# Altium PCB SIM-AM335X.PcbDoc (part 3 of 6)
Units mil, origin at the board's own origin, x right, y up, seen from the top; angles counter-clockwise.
Board outline 4041.51 x 2715.24 mil, 2 copper layers (Top Layer, Bottom Layer); 172 components, 190 nets, 855 pads, 317 vias.
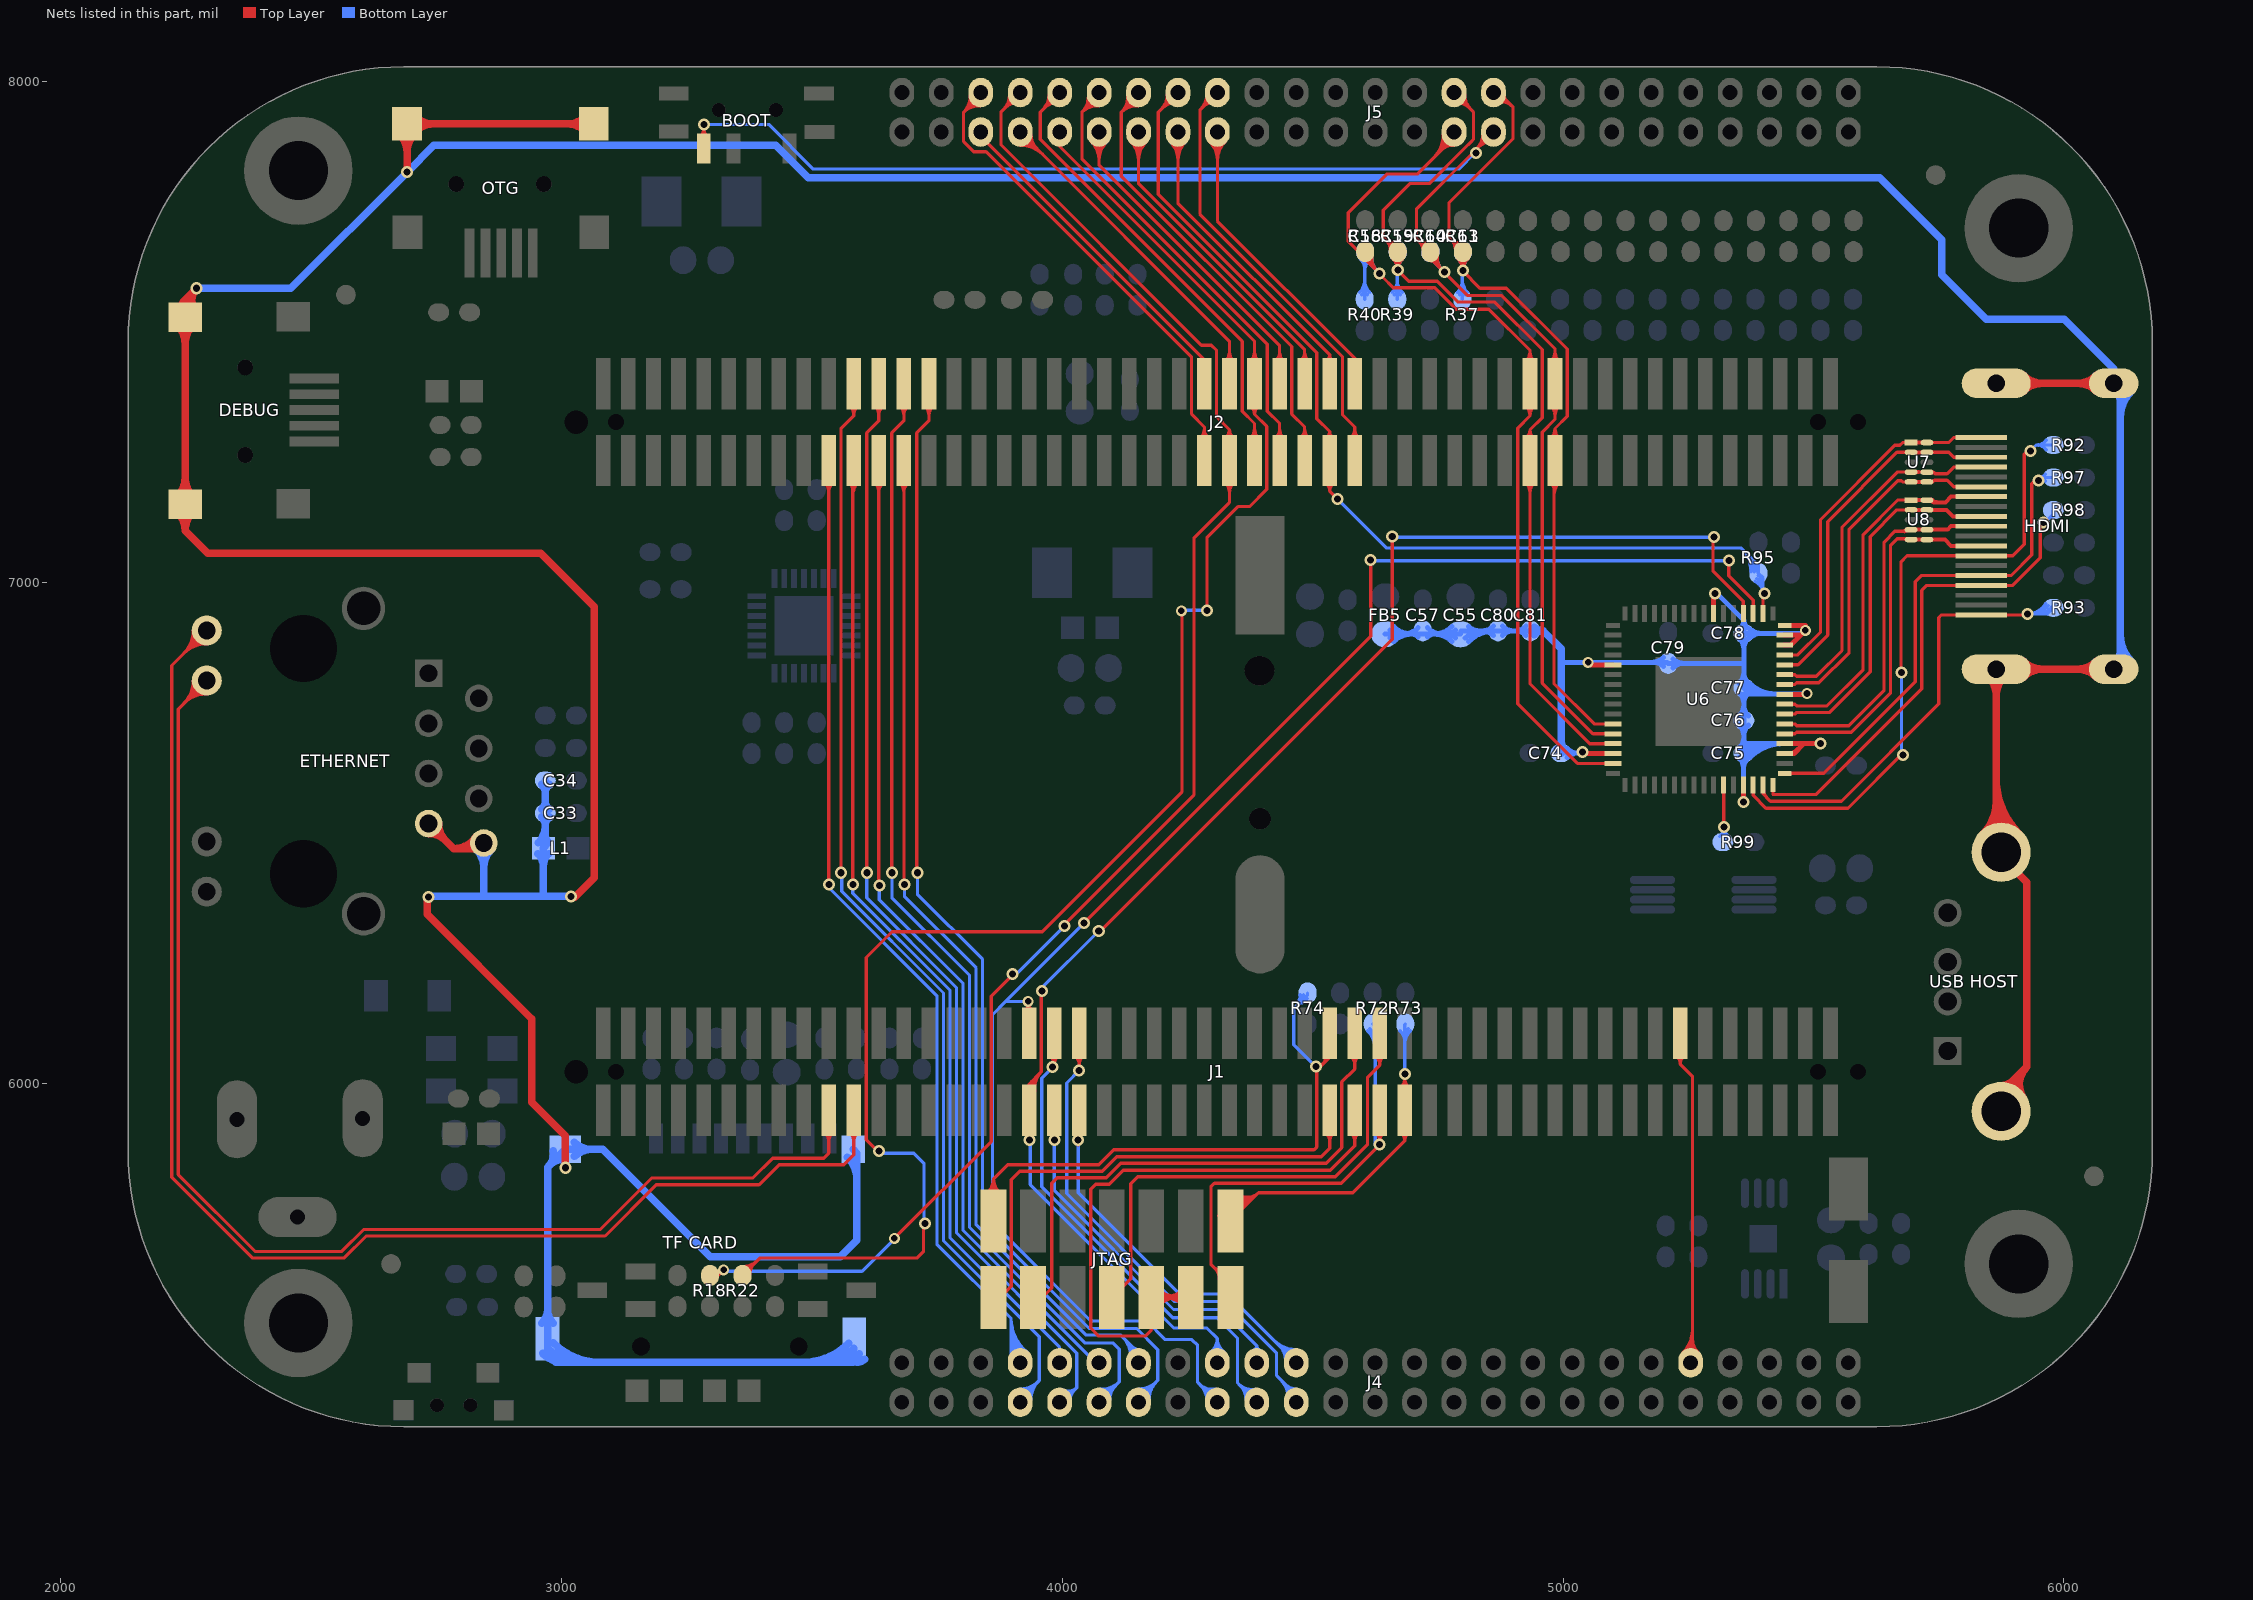
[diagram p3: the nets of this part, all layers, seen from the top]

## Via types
v1: diameter 24, hole 14, Top Layer to Bottom Layer, tented both sides, 206 vias
v2: diameter 22, hole 13, Top Layer to Bottom Layer, tented both sides, 109 vias
v3: diameter 22, hole 14, Top Layer to Bottom Layer, tented both sides, 2 vias

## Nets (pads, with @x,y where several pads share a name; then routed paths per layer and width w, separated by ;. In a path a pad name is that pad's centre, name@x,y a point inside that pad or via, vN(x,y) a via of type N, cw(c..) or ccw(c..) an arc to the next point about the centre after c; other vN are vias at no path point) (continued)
GND_EARTH: "TF CARD.10" "TF CARD.11" "TF CARD.12" "TF CARD.13" "USB HOST.5" "USB HOST.6" C33.1 C34.1 DEBUG.6 DEBUG.7 ETHERNET.7 ETHERNET.8 HDMI.20 HDMI.21 HDMI.22 HDMI.23 L1.1 OTG.6 OTG.7 | length 15044.9
  Top Layer w15: DEBUG.6@2233.42,7172.5 ccw(c2195.82,7210.1) 2249,7210.1 ccw(c2302.18,7210.1) DEBUG.6@2264.58,7172.5 ; DEBUG.7@2233.42,7514.5 cw(c2195.82,7476.89) 2249,7476.89 cw(c2302.18,7476.89) DEBUG.7@2264.58,7514.5 ; DEBUG.6@2233.48,7141.29 cw(c2196.45,7104) 2249,7104 ; DEBUG.7@2239.51,7549.95 ccw(c2232.32,7565) 2249,7565 ; DEBUG.7@2246.79,7524.99 cw(c2269.55,7543.8) 2248.67,7564.67 ; DEBUG.7@2258.35,7534.55 cw(c2282.32,7554.35) 2260.34,7576.34 ; DEBUG.7@2258.49,7549.95 cw(c2265.68,7565) 2249,7565 ; DEBUG.6@2264.52,7141.29 ccw(c2301.55,7104) 2249,7104 ; DEBUG.7@2269.92,7544.1 cw(c2295.09,7564.91) v1(2272,7588) 2249,7565 ; OTG.6@2676.35,7896.49 cw(c2638.74,7858.88) 2691.92,7858.88 cw(c2745.1,7858.88) OTG.6@2707.5,7896.49 ; v1@2691.92,7823 OTG.6@2691.92,7916 OTG.7@3065.07,7916 ; OTG.6@2707.5,7900.42 cw(c2745.1,7862.82) 2745.1,7916 cw(c2745.1,7969.18) OTG.6@2707.5,7931.58 ; v1(2735,6373) 2732,6370 2732,6338 2941,6129 2941,5963 3007.91,5896.09 v1@3007.91,5832 ; ETHERNET.7@2735,6499.2 cw(c2735,6450.92) 2769.14,6485.06 cw(c2803.28,6519.2) ETHERNET.7@2755,6519.2 ; ETHERNET.7@2735,6519.2 2785,6469.2 ; 2813.94,6469.2 ccw(c2813.94,6502.45) ETHERNET.8@2841.11,6483.28 ; ETHERNET.8@2828.86,6491.93 cw(c2785,6522.87) 2785,6469.2 ; ETHERNET.8@2835,6469.2 2785,6469.2 ; v1@3027,6372 3065.97,6410.97 3065.97,6952.03 2959,7059 2294,7059 2249,7104 ; OTG.7@3049.5,7900.42 ccw(c3011.89,7862.82) 3011.89,7916 ccw(c3011.89,7969.18) OTG.7@3049.5,7931.58 ; 5838.24,6498.32 ccw(c5773.81,6562.74) 5864.92,6562.74 ; 5848.84,6487.71 ccw(c5810.03,6526.53) 5864.92,6526.53 ; HDMI.20@5849.35,6811.83 cw(c5811.74,6774.22) 5864.92,6774.22 cw(c5918.1,6774.22) HDMI.20@5880.5,6811.83 ; 5864.92,6537.49 ccw(c5950.32,6537.49) 5889.93,6477.11 ; 5864.92,6573.7 ccw(c5986.53,6573.7) 5900.54,6487.71 ; 5864.92,6609.92 ccw(c6022.74,6609.92) 5911.15,6498.32 ; HDMI.21@5864.92,7398.27 HDMI.22@6099.57,7398.27 ; 5874.69,5944.54 5874.69,5982.08 5926,6033.39 ; 5874.69,5996.1 ccw(c5874.69,6029.94) 5898.62,6006.01 ; 5893.07,5955.8 cw(c5928.23,5977.33) 5899.08,6006.47 ; 5905.87,5963.63 cw(c5944.92,5987.55) 5912.54,6019.93 ; 5918.66,5971.47 cw(c5961.62,5997.77) 5926,6033.39 ; HDMI.20@5919.87,6811.83 cw(c5957.47,6774.22) 5957.47,6827.4 cw(c5957.47,6880.58) HDMI.20@5919.87,6842.98 ; HDMI.21@5919.87,7382.69 cw(c5957.47,7345.09) 5957.47,7398.27 cw(c5957.47,7451.45) HDMI.21@5919.87,7413.84 ; HDMI.23@6064.31,6811.83 ccw(c6026.7,6774.22) 6026.7,6827.4 ccw(c6026.7,6880.58) HDMI.23@6064.31,6842.98 ; HDMI.22@6064.31,7382.69 ccw(c6026.7,7345.09) 6026.7,7398.27 ccw(c6026.7,7451.45) HDMI.22@6064.31,7413.84 ; HDMI.23@6099.57,6827.4 HDMI.20@5864.92,6827.4 5864.92,6471.64 5874.69,6461.87 5874.69,6453.31 5926,6402 5926,6033.39 ; 2249,7104 DEBUG.6@2249,7156.92 DEBUG.7@2249,7530.07 2249,7565
  Bottom Layer w15: v1(2272,7588) 2460,7588 v1(2692,7820) 2745.5,7873.5 3428.5,7873.5 3493.25,7808.75 5632.25,7808.75 5756,7685 5756,7615 5845,7526 6001,7526 6099.57,7427.43 HDMI.22@6099.57,7398.27 6113,7384.83 6113,6840.84 HDMI.23@6099.57,6827.4 ; v1@2744.23,6373.77 2845.2,6373.77 ; ETHERNET.8@2831.06,6466.26 cw(c2796.92,6432.12) 2845.2,6432.12 cw(c2893.48,6432.12) ETHERNET.8@2859.34,6466.26 ; ETHERNET.8@2845.2,6480.4 2845.2,6373.77 ; L1.1@2953.39,6459.39 cw(c2927.79,6433.79) 2964,6433.79 cw(c3000.21,6433.79) L1.1@2974.61,6459.39 ; L1.1@2953.89,6480.61 ccw(c2919.84,6514.66) 2968,6514.66 ; C33.1@2960.58,6532.58 cw(c2942.65,6514.65) 2968,6514.65 ; C33.1@2960.58,6547.42 ccw(c2942.65,6565.35) 2968,6565.35 ccw(c2993.35,6565.35) C33.1@2975.42,6547.42 ; C34.1@2960.58,6597.58 cw(c2942.65,6579.65) 2968,6579.65 cw(c2993.35,6579.65) C34.1@2975.42,6597.58 ; 2961.08,5521.83 ccw(c2933.56,5549.36) 2972.48,5549.36 ccw(c3011.4,5549.36) 2983.88,5521.83 ; 2962.67,5461.25 ccw(c3005.82,5504.4) 3005.82,5443.38 ; 2964,6376.77 L1.1@2964,6470 2968,6474 C33.1@2968,6540 C34.1@2968,6605 ; 2968,6497.76 ccw(c2992.26,6497.76) L1.1@2975.11,6480.61 ; 2973.27,5471.86 ccw(c3042.03,5540.62) 3042.03,5443.38 ; 2974.45,5835.24 ccw(c2949.85,5859.83) 2984.18,5865.46 ; C33.1@2975.42,6532.58 ccw(c2993.35,6514.65) 2968,6514.65 ; 2976.45,5837.24 cw(c3003.98,5809.72) 3003.98,5848.64 ; 2983.88,5482.46 ccw(c3078.25,5576.83) 3078.25,5443.38 ; v1(3019,6373.77) 2845.2,6373.77 ; 3026.03,5854.52 cw(c3060.28,5820.27) 3060.28,5868.7 cw(c3060.28,5917.13) 3026.03,5882.88 ; 3481.04,5443.38 ccw(c3481.04,5574.27) 3573.6,5481.71 ; 3517.25,5443.38 ccw(c3517.25,5538.06) 3584.21,5471.11 ; 3553.47,5443.38 ccw(c3553.47,5501.85) 3594.81,5460.5 ; 3571.32,5853.36 cw(c3526.21,5808.26) 3590,5808.26 ; 3582.72,5868.7 3590,5861.42 3590,5687 3557,5654 3297,5654 3082.3,5868.7 3007.91,5868.7 2972.48,5833.27 2972.48,5490.75 2972.48,5459.52 2988.62,5443.38 3582.38,5443.38 3585,5446 ; 3589.68,5443.38 ccw(c3589.68,5465.63) 3605.42,5449.9 ; HDMI.21@5861.28,7401.91 HDMI.21@5864.92,7398.27 ; HDMI.23@6103.68,6842.98 ccw(c6081.16,6865.49) 6113,6865.49 ; HDMI.22@6103.68,7382.69 cw(c6081.16,7360.18) 6113,7360.18 ; 6113,6859.46 ccw(c6151.31,6859.46) HDMI.23@6124.22,6832.37 ; 6113,6895.67 ccw(c6187.52,6895.67) HDMI.23@6134.83,6842.98 ; 6113,7330 cw(c6187.52,7330) HDMI.22@6134.83,7382.69 ; 6113,7366.21 cw(c6151.31,7366.21) HDMI.22@6124.22,7393.3
  other v1: 3008,5832
GNDA_ADC: J1.88 J4.42 | length 869.5
  Top Layer w6.5: J1.88@5226.55,6055.41 cw(c5212.2,6039) 5234,6039 ; J1.88@5234,6100.54 5234,6039 ; J4.42@5239.57,5462.76 ccw(c5194.3,5508.03) 5258.32,5508.03 ; J1.88@5241.45,6055.41 ccw(c5255.8,6039) 5234,6039 ; J4.42@5244.17,5458.17 ccw(c5210,5492.33) 5258.32,5492.33 ; J4.42@5248.76,5453.57 ccw(c5225.69,5476.64) 5258.32,5476.64 ; J4.42@5254.67,5442.74 5258.32,5446.39 5258.32,6014.68 5234,6039 ; 5258.32,5474.72 ccw(c5281.73,5474.72) J4.42@5265.17,5458.17 ; 5258.32,5490.41 ccw(c5297.42,5490.41) J4.42@5269.77,5462.76
GPIO0_7: J2.50 J5.5 | length 687.4
  Top Layer w6.5: J5.5@3837.48,7900 3837.48,7891.52 4284,7445 J2.50@4284,7397.54
GPIO1_16: J2.51 J5.8 R18.1 | length 3370.7
  Top Layer w6.5: R18.1@3296.8,5617 3313,5617 v2(3324,5628) ; v2(3665,5691) 3858.32,5884.32 3858.32,6174.32 v1@3906,6222 ; 3883.24,7945.76 ccw(c3855.19,7973.82) J5.8@3894.86,7973.82 ; 3885.54,7948.06 cw(c3912.22,7921.38) J5.8@3915.09,7959.01 ; 3894.34,7956.86 ccw(c3877.38,7973.82) J5.8@3901.36,7973.82 ; 3895.55,7958.07 cw(c3913.64,7939.97) J5.8@3915.58,7965.49 ; J5.8@3916.22,7978.74 3878,7940.52 3878,7874 4278,7474 4298,7474 4308.32,7463.68 4308.32,7331.68 4334,7306 ; v1(4005,6315) 4005,6318 4263,6576 4263,7089 4334,7160 J2.51@4334,7244 4334,7306 ; J2.51@4326,7199.38 cw(c4306.68,7180.06) 4334,7180.06 cw(c4361.32,7180.06) J2.51@4342,7199.38 ; J2.51@4326.44,7289.03 ccw(c4311.19,7306) 4334,7306 ; J2.51@4341.56,7289.03 cw(c4356.81,7306) 4334,7306
  Bottom Layer w6.5: v2@3324,5625.5 3600.5,5625.5 3659.54,5684.54 v2@3659.54,5693 ; v1@3906,6222 3912,6222 v1(4005,6315)
  other v1: 3901,6219
GPIO1_17: J2.54 J5.9 R22.1 | length 3588.5
  Top Layer w6.5: R22.1@3361.8,5617 3396.8,5652 3711,5652 3723,5664 3723,5718 v1(3726,5721) ; R22.1@3361.8,5628.25 ccw(c3361.8,5655.41) 3381.01,5636.2 ; R22.1@3361.8,5634.75 ccw(c3361.8,5677.6) 3392.11,5647.3 ; R22.1@3376.55,5620 cw(c3404.92,5620) 3384.86,5640.06 ; v1@3639,5862 3630,5871 3626,5871 3609,5888 3609,6251.76 3660.24,6303 3960,6303 4239,6582 v2@4239,6941 ; J5.9@3994.96,7900 3994.96,7871.04 4384,7482 J2.54@4384,7397.54 4384,7336.39 ; v1@4289,6937 v1(4289,6945) 4289,7090.11 4350.89,7152 4374,7152 4408.32,7186.32 4408.32,7312.07 4384,7336.39 ; J2.54@4376,7442.16 ccw(c4356.68,7461.48) 4384,7461.48 ccw(c4411.32,7461.48) J2.54@4392,7442.16 ; J2.54@4376.65,7352.32 cw(c4363.06,7336.39) 4384,7336.39 ; J2.54@4391.35,7352.32 ccw(c4404.94,7336.39) 4384,7336.39
  Bottom Layer w6.5: v1@3638,5861 3704,5861 3724,5841 v1@3724,5721 ; v2(4238,6944) 4239,6945 v1(4289,6945)
  other v1: 3634,5865
GPIO1_18: J2.53 J5.10 | length 1077.1
  Top Layer w6.5: 3961.98,7945.76 ccw(c3933.93,7973.82) J5.10@3973.6,7973.82 ; 3963.74,7947.52 cw(c3991.62,7919.64) J5.10@3994.05,7958.99 ; 3973.08,7956.86 ccw(c3956.12,7973.82) J5.10@3980.1,7973.82 ; 3973.93,7957.71 cw(c3992.8,7938.84) J5.10@3994.45,7965.48 ; J5.10@3994.96,7978.74 3956,7939.78 3956,7885.45 4359.68,7481.77 4359.68,7342.32 4384,7318.01 J2.53@4384,7244 ; J2.53@4376,7288.62 ccw(c4356.68,7307.94) 4384,7307.94 ccw(c4411.32,7307.94) J2.53@4392,7288.62
GPIO1_19: J2.56 J5.11 | length 831.9
  Top Layer w6.5: J5.11@4058.6,7879.98 cw(c4022.14,7843.52) 4073.7,7843.52 cw(c4125.26,7843.52) J5.11@4088.8,7879.98 ; J5.11@4063.2,7884.57 cw(c4037.84,7859.21) 4073.7,7859.21 cw(c4109.57,7859.21) J5.11@4084.21,7884.57 ; J5.11@4073.7,7900 4073.7,7833.3 4434,7473 J2.56@4434,7397.54 ; J2.56@4426,7442.16 ccw(c4406.68,7461.48) 4434,7461.48 ccw(c4461.32,7461.48) J2.56@4442,7442.16
GPIO1_21: J2.55 J5.12 | length 1080.6
  Top Layer w6.5: 4049.83,7949.76 ccw(c4027.95,7971.65) J5.12@4058.86,7973.12 ; 4049.96,7949.89 cw(c4071.94,7927.91) J5.12@4073.13,7958.97 ; J5.12@4052.37,7972.81 cw(c4008.1,7970.71) 4039.44,7939.37 cw(c4071.16,7907.65) J5.12@4072.88,7952.48 ; J5.12@4073.7,7978.74 4073.7,7973.63 4039.34,7939.28 4039.34,7846.66 4409.68,7476.32 4409.68,7342.32 4434,7318.01 J2.55@4434,7244 ; J2.55@4426,7288.62 ccw(c4406.68,7307.94) 4434,7307.94 ccw(c4461.32,7307.94) J2.55@4442,7288.62
GPIO1_22: J2.58 J5.13 | length 820
  Top Layer w6.5: J5.13@4137.34,7879.98 cw(c4100.88,7843.52) 4152.44,7843.52 cw(c4204,7843.52) J5.13@4167.54,7879.98 ; J5.13@4141.94,7884.57 cw(c4116.58,7859.21) 4152.44,7859.21 cw(c4188.31,7859.21) J5.13@4162.95,7884.57 ; J5.13@4152.44,7900 4152.44,7796.63 4484,7465.08 J2.58@4484,7397.54 ; J2.58@4476,7442.16 ccw(c4456.68,7461.48) 4484,7461.48 ccw(c4511.32,7461.48) J2.58@4492,7442.16
GPIO1_23: J2.57 J5.14 | length 1068.7
  Top Layer w6.5: 4128.57,7949.76 ccw(c4106.69,7971.65) J5.14@4137.6,7973.12 ; 4128.7,7949.89 cw(c4150.68,7927.91) J5.14@4151.87,7958.97 ; J5.14@4131.11,7972.81 cw(c4086.84,7970.71) 4118.18,7939.37 cw(c4149.9,7907.65) J5.14@4151.62,7952.48 ; J5.14@4152.44,7978.74 4152.44,7973.63 4118.08,7939.28 4118.08,7811.92 4458.32,7471.68 4458.32,7336.68 4484,7311 J2.57@4484,7244 ; J2.57@4476,7288.62 ccw(c4456.68,7307.94) 4484,7307.94 ccw(c4511.32,7307.94) J2.57@4492,7288.62
GPIO1_24: J2.60 J5.15 | length 792.1
  Top Layer w6.5: J5.15@4216.08,7879.98 cw(c4179.62,7843.52) 4231.18,7843.52 cw(c4282.74,7843.52) J5.15@4246.28,7879.98 ; J5.15@4220.68,7884.57 cw(c4195.32,7859.21) 4231.18,7859.21 cw(c4267.05,7859.21) J5.15@4241.69,7884.57 ; J5.15@4231.18,7900 4231.18,7757.82 4534,7455 ; J2.60@4527.84,7443.65 ccw(c4520.47,7455) 4534,7455 ; J2.60@4534,7397.54 4534,7455 ; J2.60@4540.16,7443.65 cw(c4547.53,7455) 4534,7455
GPIO1_26: J2.62 J5.17 | length 753.3
  Top Layer w6.5: J5.17@4294.82,7879.98 cw(c4258.36,7843.52) 4309.92,7843.52 cw(c4361.48,7843.52) J5.17@4325.02,7879.98 ; J5.17@4299.42,7884.57 cw(c4274.06,7859.21) 4309.92,7859.21 cw(c4345.79,7859.21) J5.17@4320.43,7884.57 ; J5.17@4309.92,7900 4309.92,7722.08 4584,7448 J2.62@4584,7397.54
GPIO1_27: J2.61 J5.18 | length 998.6
  Top Layer w6.5: 4276.94,7945.76 ccw(c4248.89,7973.82) J5.18@4288.57,7973.82 ; 4281.68,7950.5 cw(c4303.29,7928.89) J5.18@4307.75,7959.12 ; 4288.04,7956.86 ccw(c4271.08,7973.82) J5.18@4295.07,7973.82 ; J5.18@4309.92,7978.74 4275,7943.82 4275,7736.08 4559.68,7451.4 4559.68,7335.32 4584,7311 J2.61@4584,7244 ; J2.61@4576,7288.62 ccw(c4556.68,7307.94) 4584,7307.94 ccw(c4611.32,7307.94) J2.61@4592,7288.62
GPIO2_0: J2.49 J5.6 | length 1130.8
  Top Layer w6.5: 3813.61,7949.76 ccw(c3791.73,7971.65) J5.6@3822.64,7973.11 ; 3813.74,7949.89 cw(c3835.72,7927.91) J5.6@3836.91,7958.97 ; J5.6@3816.15,7972.81 cw(c3771.88,7970.71) 3803.22,7939.37 cw(c3834.94,7907.65) J5.6@3836.66,7952.48 ; J5.6@3837.48,7978.74 3837.48,7973.63 3803.12,7939.28 3803.12,7880.85 3823.25,7860.72 3848.02,7860.72 4258.32,7450.43 4258.32,7336.68 4284,7311 J2.49@4284,7244 ; J2.49@4276,7288.62 ccw(c4256.68,7307.94) 4284,7307.94 ccw(c4311.32,7307.94) J2.49@4292,7288.62
GPIO2_1: J2.52 J5.7 | length 880.9
  Top Layer w6.5: J5.7@3916.22,7873.72 cw(c3916.22,7810.28) 3961.08,7855.14 ; J5.7@3916.22,7880.22 cw(c3916.22,7832.48) 3949.98,7866.24 ; J5.7@3916.22,7886.72 cw(c3916.22,7854.67) 3938.89,7877.33 ; J5.7@3916.22,7900 4334,7482.22 J2.52@4334,7397.54 ; J5.7@3931.08,7895.08 ccw(c3955.06,7895.08) 3938.1,7878.12 ; J5.7@3937.58,7895.08 ccw(c3977.25,7895.08) 3949.2,7867.02 ; J2.52@4326,7442.16 ccw(c4306.68,7461.48) 4334,7461.48 ccw(c4361.32,7461.48) J2.52@4342,7442.16
GPMC_ADVN_ALE: J2.21 J4.10 | length 2059.3
  Top Layer w6.5: J2.21@3576,7199.38 cw(c3561.49,7184.87) 3582.01,7184.87 ; v1(3582,6398) 3582.01,7244.13 J2.21@3584,7273.54 ; 3582.01,7175.26 cw(c3616.13,7175.26) J2.21@3592,7199.38 ; 3582.01,7190.95 cw(c3600.44,7190.95) J2.21@3587.41,7203.98
  Bottom Layer w6.5: v1(3582,6398) 3582,6380.29 3776,6186.29 3776,5692 3994.83,5473.17 J4.10@3994.83,5442.74
GPMC_BE0N_CLE: J2.26 J4.11 | length 2503.3
  Top Layer w6.5: v1@3665,6419 3665,6419.68 3659.68,6425 3659.68,7299.22 3684,7323.54 J2.26@3684,7397.54 ; J2.26@3676,7352.93 cw(c3656.68,7333.61) 3684,7333.61 cw(c3711.32,7333.61) J2.26@3692,7352.93 ; J4.11@4073.57,5364 J4.11@4073.57,5389.23
  Bottom Layer w6.5: v1@3659.68,6425 v1@3661.84,6422.84 ; v1(3660,6421) 3660,6371.25 3815,6216.25 3815,5712.84 4045.83,5482.02 4101.98,5482.02 4114,5470 4114,5404.43 ; J4.11@4073.57,5364 4114,5404.43 ; J4.11@4074.24,5377.25 ccw(c4076.29,5402.39) 4094.12,5384.56 ; J4.11@4074.77,5383.73 ccw(c4077.78,5420.77) 4104.06,5394.49 ; J4.11@4075.3,5390.21 ccw(c4079.27,5439.16) 4114,5404.43 ; J4.11@4088.42,5368.92 cw(c4112.41,5368.92) 4095.45,5385.88 ; J4.11@4094.92,5368.92 cw(c4134.6,5368.92) 4106.55,5396.98
GPMC_BE1N: J2.23 J4.12 | length 2029.8
  Top Layer w6.5: J2.23@3626,7199.38 cw(c3606.68,7180.06) 3634,7180.06 cw(c3661.32,7180.06) J2.23@3642,7199.38 ; v1@3634,6396 J2.23@3634,7244
  Bottom Layer w6.5: v1(3635,6396) 3635,6367.23 3802,6200.23 3802,5707.46 4066.72,5442.74 J4.12@4073.57,5442.74
GPMC_CSN0: J2.22 J4.7 | length 2404.3
  Top Layer w6.5: v1(3558,6421) 3558.32,6421.32 3558.32,7307.32 3584,7333 J2.22@3584,7397.54 ; J2.22@3576,7352.93 cw(c3556.68,7333.61) 3584,7333.61 cw(c3611.32,7333.61) J2.22@3592,7352.93
  Bottom Layer w6.5: v1(3558,6421) 3559.75,6419.25 3559.75,6384.15 3763,6180.9 3763,5686 3954,5495 3954,5407.02 3916.09,5369.11 J4.7@3916.09,5364 ; J4.7@3916.09,5383.78 ccw(c3916.09,5419.2) 3941.13,5394.15 ; J4.7@3916.09,5390.28 ccw(c3916.09,5441.39) 3952.23,5405.25 ; J4.7@3930.94,5368.92 cw(c3967.25,5368.92) 3941.58,5394.6 ; J4.7@3937.44,5368.92 cw(c3989.45,5368.92) 3952.67,5405.69
GPMC_OEN_REN: J2.24 J4.9 | length 2350.2
  Top Layer w6.5: v1(3610,6421) 3609,6422 3609.68,6422.68 3609.68,7299.22 3634,7323.54 J2.24@3634,7397.54 ; J2.24@3626,7352.93 cw(c3606.68,7333.61) 3634,7333.61 cw(c3661.32,7333.61) J2.24@3642,7352.93
  Bottom Layer w6.5: v1(3610,6421) 3610,6370.67 3789,6191.67 3789,5702.07 4029.18,5461.89 4029.18,5393 ; J4.9@3994.83,5364 4000.18,5364 4029.18,5393 ; J4.9@4000.97,5382.45 ccw(c4008.93,5399.98) 4022.55,5386.36 ; J4.9@4003.66,5388.37 ccw(c4013.08,5409.1) 4029.18,5393 ; J4.9@4016.18,5368.92 cw(c4042.93,5368.92) 4024.02,5387.83
GPMC_WAIT0: J2.28 J4.13 | length 2497.1
  Top Layer w6.5: v1@3709.68,6418.32 3709.68,7299.22 3734,7323.54 J2.28@3734,7397.54 ; J2.28@3726,7352.93 cw(c3706.68,7333.61) 3734,7333.61 cw(c3761.32,7333.61) J2.28@3742,7352.93
  Bottom Layer w6.5: v1(3711,6421) 3711,6378 3841,6248 3841,5723.61 4053.61,5511 4148.66,5511 4191,5468.66 4191,5407.8 4152.31,5369.11 J4.13@4152.31,5364 ; J4.13@4152.31,5383.78 ccw(c4152.31,5419.2) 4177.35,5394.15 ; J4.13@4152.31,5390.28 ccw(c4152.31,5441.39) 4188.45,5405.25 ; J4.13@4167.16,5368.92 cw(c4203.48,5368.92) 4177.8,5394.6 ; J4.13@4173.66,5368.92 cw(c4225.67,5368.92) 4188.9,5405.69
GPMC_WEN: J2.19 J4.8 | length 2284.9
  Top Layer w6.5: J2.19@3526,7199.38 cw(c3506.68,7180.06) 3534,7180.06 cw(c3561.32,7180.06) J2.19@3542,7199.38 ; v1(3534,6398) J2.19@3534,7244
  Bottom Layer w6.5: v1(3534,6398) 3534,6391.52 3750,6175.52 3750,5679 3898,5531 ; 3898,5476.06 ccw(c3939.37,5476.06) J4.8@3913.14,5444.07 ; 3898,5489.8 ccw(c3950.63,5489.8) J4.8@3917.26,5449.1 ; 3898,5503.53 ccw(c3961.89,5503.53) J4.8@3921.38,5454.12 ; 3898,5517.26 ccw(c3973.14,5517.26) J4.8@3925.5,5459.15 ; J4.8@3916.09,5442.74 3898,5460.83 3898,5531 ; J4.8@3929.63,5464.18 cw(c3984.4,5531) 3898,5531
GPMC_WPN: J2.25 J4.14 | length 2220.8
  Top Layer w6.5: J2.25@3676,7199.38 cw(c3656.68,7180.06) 3684,7180.06 cw(c3711.32,7180.06) J2.25@3692,7199.38 ; v1@3684,6389.24 J2.25@3684,7244
  Bottom Layer w6.5: v1(3685,6398) 3685,6374 3828,6231 3828,5718.23 4048.23,5498 4117,5498 4152.31,5462.69 J4.14@4152.31,5442.74 ; 4119.72,5495.28 cw(c4076.58,5452.15) J4.14@4137.48,5448.54 ; 4129.95,5485.05 cw(c4095.9,5451) J4.14@4143.97,5448.16 ; 4140.18,5474.82 cw(c4115.21,5449.86) J4.14@4150.45,5447.77 ; 4141.51,5473.49 ccw(c4152.31,5484.29) J4.14@4152.31,5469.02
GR_N: ETHERNET.10 J1.19 | length 2813.1
  Top Layer w6.5: ETHERNET.10@2265.34,6804.83 cw(c2200.76,6804.83) 2246.42,6759.16 cw(c2292.09,6713.5) ETHERNET.10@2292.09,6778.08 ; ETHERNET.10@2271.84,6804.83 cw(c2222.95,6804.83) 2257.52,6770.26 cw(c2292.09,6735.69) ETHERNET.10@2292.09,6784.58 ; ETHERNET.10@2278.34,6804.83 cw(c2245.14,6804.83) 2268.62,6781.36 cw(c2292.09,6757.88) ETHERNET.10@2292.09,6791.08 ; ETHERNET.10@2292.09,6804.83 2235,6747.74 2235,5818.38 2388.38,5665 2561.62,5665 2605.31,5708.69 3077.69,5708.69 3180.5,5811.5 3382.5,5811.5 3422,5851 3524,5851 3534,5861 J1.19@3534,5947 ; J1.19@3526,5902.38 cw(c3506.68,5883.06) 3534,5883.06 cw(c3561.32,5883.06) J1.19@3542,5902.38
GR_P: ETHERNET.9 J1.21 | length 2997.2
  Top Layer w6.5: ETHERNET.9@2265.34,6904.83 cw(c2200.76,6904.83) 2246.42,6859.16 cw(c2292.09,6813.5) ETHERNET.9@2292.09,6878.08 ; ETHERNET.9@2271.84,6904.83 cw(c2222.95,6904.83) 2257.52,6870.26 cw(c2292.09,6835.69) ETHERNET.9@2292.09,6884.58 ; ETHERNET.9@2278.34,6904.83 cw(c2245.14,6904.83) 2268.62,6881.36 cw(c2292.09,6857.88) ETHERNET.9@2292.09,6891.08 ; ETHERNET.9@2292.09,6904.83 2222,6834.74 2222,5813 2383,5652 2567,5652 2610.69,5695.69 3087.38,5695.69 3189.69,5798 3394.77,5798 3434.77,5838 3564,5838 3584,5858 J1.21@3584,5947 ; J1.21@3576,5902.38 cw(c3556.68,5883.06) 3584,5883.06 cw(c3611.32,5883.06) J1.21@3592,5902.38
HDMI_1V8: C55.2 C57.1 C74.1 C75.1 C76.1 C77.1 C78.1 C79.1 C80.1 C81.1 FB5.2 U6.5 U6.14 U6.29 U6.35 U6.36 U6.41 U6.46 U6.47 U6.48 U6.55 | length 3905.8
  Top Layer w10: v1@5039.01,6658.99 U6.14@5100,6658.99 ; v2(5050,6841) 5054.77,6836.23 U6.5@5100,6836.23 ; U6.55@5300.85,6938.62 v1@5300.85,6979 ; v1@5359.93,6560.07 U6.29@5359.93,6595.99 ; U6.35@5442.63,6658.99 5460.99,6658.99 5480.69,6678.69 ; U6.36@5442.63,6678.69 5480.69,6678.69 ; U6.41@5442.63,6777.15 v3@5491,6777.15 ; U6.46@5442.63,6875.61 5454.61,6875.61 5474.31,6895.31 ; U6.47@5442.63,6895.31 5474.31,6895.31 ; U6.48@5442.63,6915 5484,6915 v2(5484,6905) 5474.31,6895.31 ; U6.35@5454.36,6658.99 ccw(c5454.36,6675) 5465.68,6663.68 ; v1(5514,6679) 5513.69,6678.69 5480.69,6678.69
  Bottom Layer w10: FB5.2@4645,6897.5 C55.2@4795,6897.5 ; FB5.2@4654.63,6889.37 cw(c4674.26,6869.74) 4674.26,6897.5 cw(c4674.26,6925.26) FB5.2@4654.63,6905.63 ; FB5.2@4661.7,6882.3 cw(c4698.41,6845.59) 4698.41,6897.5 cw(c4698.41,6949.41) FB5.2@4661.7,6912.7 ; 4680.17,6897.5 ccw(c4680.17,6940.83) C57.1@4710.81,6910.19 ; 4697.06,6897.5 cw(c4697.06,6878.06) C57.1@4710.81,6891.81 ; C57.1@4729.19,6891.81 cw(c4742.94,6878.06) 4742.94,6897.5 ; C57.1@4729.19,6910.19 ccw(c4759.83,6940.83) 4759.83,6897.5 ; C55.2@4778.3,6882.3 ccw(c4741.59,6845.59) 4741.59,6897.5 ccw(c4741.59,6949.41) C55.2@4778.3,6912.7 ; C55.2@4785.37,6889.37 ccw(c4765.74,6869.74) 4765.74,6897.5 ccw(c4765.74,6925.26) C55.2@4785.37,6905.63 ; C55.2@4796,6903.5 4801.5,6904 C80.1@4870,6904 C81.1@4935,6904 ; C55.2@4804.63,6889.37 cw(c4839.96,6854.04) 4839.96,6904 ; C55.2@4811.7,6882.3 cw(c4864.1,6829.9) C80.1@4864.1,6904 ; C55.2@4811.7,6912.7 ccw(c4832.71,6933.71) 4832.71,6904 ; C80.1@4860.81,6894.81 ccw(c4838.62,6872.62) 4838.62,6904 ccw(c4838.62,6935.38) C80.1@4860.81,6913.19 ; C80.1@4879.19,6894.81 cw(c4901.38,6872.62) 4901.38,6904 cw(c4901.38,6935.38) C80.1@4879.19,6913.19 ; C81.1@4925.81,6894.81 ccw(c4903.62,6872.62) 4903.62,6904 ccw(c4903.62,6935.38) C81.1@4925.81,6913.19 ; C74.1@4996,6660 v1@5039.01,6660 ; 4996,6842 4997,6841 v2(5050,6841) 5208,6841 C79.1@5210,6839 5360,6839 5361,6840 ; C74.1@5008.19,6650.81 cw(c5030.38,6628.62) 5030.38,6660 cw(c5030.38,6691.38) C74.1@5008.19,6669.19 ; 5176.2,6841 ccw(c5176.2,6875.8) C79.1@5200.81,6851.19 ; 5181.03,6841 cw(c5181.03,6813.03) C79.1@5200.81,6832.81 ; C79.1@5219.19,6829.81 cw(c5241.38,6807.62) 5241.38,6839 cw(c5241.38,6870.38) C79.1@5219.19,6848.19 ; v1@5302,6984 5361,6925 ; C75.1@5351.81,6650.81 cw(c5332.03,6631.03) 5360,6631.03 ; C75.1@5351.81,6669.19 ccw(c5329.62,6691.38) 5361,6691.38 ccw(c5392.38,6691.38) C75.1@5370.19,6669.19 ; C76.1@5351.81,6715.81 cw(c5329.62,6693.62) 5361,6693.62 cw(c5392.38,6693.62) C76.1@5370.19,6715.81 ; C76.1@5351.81,6734.19 ccw(c5329.62,6756.38) 5361,6756.38 ccw(c5392.38,6756.38) C76.1@5370.19,6734.19 ; C77.1@5351.81,6780.81 cw(c5329.62,6758.62) 5361,6758.62 cw(c5392.38,6758.62) C77.1@5370.19,6780.81 ; C77.1@5351.81,6799.19 ccw(c5329.62,6821.38) 5361,6821.38 ccw(c5392.38,6821.38) C77.1@5370.19,6799.19 ; C78.1@5351.81,6889.66 cw(c5329.62,6867.47) 5361,6867.47 cw(c5392.38,6867.47) C78.1@5370.19,6889.66 ; C75.1@5351.98,6672.02 cw(c5368.83,6655.17) 5368.83,6679 ; C78.1@5353.15,6909.22 ccw(c5341.21,6925) 5361,6925 ; C75.1@5359.05,6664.95 cw(c5392.97,6631.03) 5392.97,6679 ; v1(5360,6562) 5360,6659 C75.1@5361,6660 5361,6680 ; 5360,6626.2 cw(c5394.8,6626.2) C75.1@5370.19,6650.81 ; C75.1@5366.12,6657.88 cw(c5417.11,6606.89) 5417.11,6679 ; C77.1@5366.12,6792.12 ccw(c5400.21,6826.21) 5400.21,6778 ; C78.1@5368.85,6909.22 cw(c5380.79,6925) 5361,6925 ; C75.1@5373.19,6650.81 cw(c5441.25,6582.75) 5441.25,6679 ; C77.1@5373.19,6799.19 ccw(c5424.36,6850.36) 5424.36,6778 ; C78.1@5373.19,6889.66 cw(c5395.38,6867.47) 5395.38,6898.85 cw(c5395.38,6930.24) C78.1@5373.19,6908.05 ; v2(5484,6905) 5477.85,6898.85 C78.1@5361,6898.85 ; v3@5491,6778 C77.1@5373,6778 ; v1(5514,6679) 5362,6679 5361,6680 ; 5361,6680 C76.1@5361,6725 5361,6777 5362,6778 C77.1@5373,6778 ; 5361,6840 C78.1@5361,6898.85 ; 5361,6840 C77.1@5361,6790 C77.1@5373,6778 ; C78.1@5361,6898.85 5361,6925
  Bottom Layer w15: C81.1@4935,6904 4960,6904 ; C81.1@4942.5,6896.65 cw(c4960,6879.49) 4960,6904 ; C81.1@4942.5,6911.35 ccw(c4960,6928.51) 4960,6904 ; C74.1@4988.58,6667.42 ccw(c4970.65,6685.35) 4996,6685.35 ccw(c5021.35,6685.35) C74.1@5003.42,6667.42 ; C74.1@4996,6660 4996,6842 4996,6868 4960,6904
  other v1: 5039,6662 5303,6979
  other v3: 5487,6779
HDMI_CEC: HDMI.13 R92.1 U6.30 | length 1313.4
  Top Layer w6.5: U6.30@5379.63,6595.99 5379.63,6575.37 5405,6550 5569,6550 v1@5682.5,6663.5 ; v1(5676,6821) 5675,6822 5675,7042 5686.78,7053.78 HDMI.13@5835,7053.78 5897.78,7053.78 5921,7077 5921,7257 v1@5927,7263
  Bottom Layer w6.5: v1(5676,6821) 5676,6659 v1(5679,6656) ; v1(5933,7263) 5945,7275 ; R92.1@5964.55,7265.7 ccw(c5945,7249.8) 5945,7275 ; R92.1@5964.55,7284.3 cw(c5945,7300.2) 5945,7275 ; R92.1@5979,7275 5945,7275
HDMI_CLK: R99.2 U6.27 | length 161.2
  Top Layer w6.5: U6.27@5319.31,6583.02 cw(c5315.23,6578.94) 5321,6578.94 ; U6.27@5320.55,6595.99 5321,6595.54 v1@5321,6517
  Bottom Layer w6.5: R99.2@5312.43,6493.42 ccw(c5296.58,6512) v1(5321,6512) ; R99.2@5319,6482.2 5321,6484.2 v1(5321,6512) ; v1@5321,6517 v1(5321,6512) ; R99.2@5330.31,6494.38 cw(c5342.32,6512) v1(5321,6512)
HDMI_DSCL: HDMI.15 R97.2 U6.33 | length 1012.7
  Top Layer w6.5: U6.33@5442.63,6619.61 5520.61,6619.61 5703,6802 5703,7002 5715.41,7014.41 HDMI.15@5835,7014.41 5894.41,7014.41 5936,7056 5936,7198 5942,7204 v1@5943,7204
  Bottom Layer w6.5: v1(5949,7204) 5945,7204 v1@5951,7210 ; R97.2@5963.09,7202.87 ccw(c5951,7196.19) v1@5951,7210 ; R97.2@5963.09,7217.13 cw(c5951,7223.81) v1@5951,7210 ; R97.2@5979,7210 v1@5951,7210
HDMI_DSDA: HDMI.16 R98.2 U6.32 | length 976.1
  Top Layer w6.5: U6.32@5419.01,6595.99 5419.2,6595.8 5419.2,6577.19 5419.38,6577 5505,6577 5716,6788 5716,6984.72 5726,6994.72 HDMI.16@5835,6994.72 5897.72,6994.72 5953,7050 v1@5953,7120
  Bottom Layer w6.5: v1(5959,7120) 5962,7120 5979,7137 R98.2@5979,7145 ; 5969.6,7127.6 cw(c5976,7121.2) R98.2@5976,7130.25
HDMI_HPD: HDMI.19 R93.2 U6.31 | length 979.1
  Top Layer w6.5: U6.31@5399.32,6595.99 5399.32,6578.68 5414,6564 5556,6564 5750,6758 5750,6930 5755.67,6935.67 HDMI.19@5835,6935.67 5918.67,6935.67 v1@5921,6938 ; U6.31@5401.07,6584.26 ccw(c5418.75,6584.26) 5406.25,6571.75
  Bottom Layer w6.5: v1@5938.91,6938 ccw(c5938.91,6973.85) R93.2@5969.06,6954.46 ; 5950.81,6938 ccw(c5950.81,6966.19) R93.2@5974.53,6950.95 ; R93.2@5963.59,6957.98 cw(c5927,6981.5) v1(5927,6938) 5967,6938 R93.2@5979,6950
HDMI_INT: J2.59 J5.16 R95.2 U6.50 | length 2341.2
  Top Layer w6.5: 4198.2,7945.76 ccw(c4170.15,7973.82) J5.16@4209.83,7973.82 ; 4199.8,7947.35 cw(c4228.04,7919.11) J5.16@4230.33,7958.99 ; 4209.3,7956.86 ccw(c4192.34,7973.82) J5.16@4216.33,7973.82 ; 4210.05,7957.61 cw(c4229.15,7938.5) J5.16@4230.7,7965.48 ; J5.16@4231.18,7978.74 4192,7939.56 4192,7775.46 4508.32,7459.14 4508.32,7327.68 4534,7302 ; J2.59@4526.69,7198.74 cw(c4513.39,7183) 4534,7183 ; J2.59@4527.64,7289.97 ccw(c4519.45,7302) 4534,7302 ; J2.59@4540.36,7289.97 cw(c4548.55,7302) 4534,7302 ; J2.59@4541.31,7198.74 ccw(c4554.61,7183) 4534,7183 ; v1(4550,7167) 4534,7183 ; U6.50@5399.32,6938.62 v1@5399.32,6978 ; 4534,7183 J2.59@4534,7244 4534,7302
  Bottom Layer w6.5: v1(4550,7167) 4647.75,7069.25 5355.75,7069.25 5390,7035 R95.2@5390,7019 5399.32,7009.68 v1@5399.32,6978 ; 5355.63,7069.37 cw(c5308.26,7022) R95.2@5375.25,7022 ; 5366.72,7058.28 cw(c5330.45,7022) R95.2@5381.75,7022 ; 5377.82,7047.18 cw(c5352.64,7022) R95.2@5388.25,7022 ; R95.2@5383.35,7002.83 cw(c5370.23,6976.88) v1@5399.32,6976.88 ; R95.2@5386.28,7008.64 cw(c5375.57,6987.44) v1@5399.32,6987.44 ; R95.2@5389.21,7014.44 cw(c5380.91,6998.01) 5399.32,6998.01
  other v1: 5402,6979
HDMI_TX0_N: HDMI.9 U6.39 U8.2 U8.9 | length 724.7
  Top Layer w6.5: U6.39@5442.63,6737.76 5463,6737.76 5466.35,6741.11 5532.37,6741.11 5613.5,6822.24 5613.5,7092.29 5666.53,7145.32 U8.2@5695,7145.32
  Top Layer w8: U8.2@5695,7145.32 U8.9@5726.5,7145.32 5765.68,7145.32 5778.48,7132.52 HDMI.9@5835,7132.52
HDMI_TX0_P: HDMI.7 U6.40 U8.1 U8.10 | length 761.7
  Top Layer w6.5: U6.40@5442.63,6757.46 5463,6757.46 5466.35,6754.11 5526.99,6754.11 5599,6826.12 5599,7096.17 5667.83,7165 U8.1@5695,7165
  Top Layer w8: U8.1@5695,7165 U8.10@5726.5,7165 5737.18,7165 5741.68,7160.5 ; U8.10@5733.78,7163.49 cw(c5733.78,7151.63) 5742.17,7160.01 ; U8.10@5734.85,7166.07 ccw(c5748.29,7179.51) 5748.29,7160.5 ; U8.10@5735.24,7165.4 ccw(c5741.68,7167.19) 5741.68,7160.5 ; HDMI.7@5835,7171.89 5775,7171.89 5763.61,7160.5 5741.68,7160.5
HDMI_TX1_N: HDMI.6 U6.42 U7.5 U7.6 | length 721.2
  Top Layer w6.5: U6.42@5442.63,6796.84 5463,6796.84 5466.35,6800.19 5510.92,6800.19 5571,6860.27 5571,7106.62 5668.24,7203.85 5675.41,7203.85 5678,7201.26 U7.5@5695,7201.26 ; U7.6@5726.5,7201.26 5738.5,7201.26 5741.99,7204.75 ; U7.6@5734.67,7203.34 ccw(c5737.29,7209.45) 5741.99,7204.75 ; HDMI.6@5835,7191.57 5780,7191.57 5766.81,7204.76 5744.5,7204.76 5741.99,7204.75
  Top Layer w8: U7.5@5695,7201.26 U7.6@5726.5,7201.26
HDMI_TX1_P: HDMI.4 U6.43 U7.4 U7.7 | length 736
  Top Layer w6.5: U6.43@5442.63,6816.54 5463,6816.54 5466.35,6813.19 5505.53,6813.19 5556.94,6864.59 5556.94,7110.94 5666.95,7220.95 U7.4@5695,7220.95 ; 5710,7220.95 U7.7@5726.5,7220.95 5739.71,7220.95 5741.41,7219.25 ; U7.7@5734.92,7218.99 cw(c5738.14,7213.45) 5742.67,7217.98 ; U7.7@5735.59,7222.3 ccw(c5741.7,7226.88) 5741.7,7219.25 ; U7.7@5735.63,7222.25 ccw(c5741.4,7226.31) 5741.4,7219.25 ; HDMI.4@5835,7230.94 5780,7230.94 5766.81,7217.76 5743.19,7217.76 5741.7,7219.25 ; 5741.41,7219.25 5741.7,7219.25
  Top Layer w8: U7.4@5695,7220.95 5710,7220.95
HDMI_TX2_N: HDMI.3 U6.44 U7.2 U7.9 | length 710.6
  Top Layer w6.5: U6.44@5442.63,6836.23 5469.23,6836.23 5528.5,6895.5 5528.5,7122.12 5666.7,7260.32 U7.2@5695,7260.32 ; U7.9@5726.5,7260.32 5726.93,7260.75 5769.88,7260.75 5780,7250.63 HDMI.3@5835,7250.63 ; U7.9@5735.38,7258.72 cw(c5740.29,7253.81) 5740.29,7260.75
  Top Layer w8: U7.2@5695,7260.32 U7.9@5726.5,7260.32
HDMI_TX2_P: HDMI.1 U6.45 U7.1 U7.10 | length 704
  Top Layer w6.5: U6.45@5442.63,6855.92 5468.92,6855.92 5514,6901 5514,7126 5662.38,7274.38 5672.38,7274.38 5678,7280 U7.1@5695,7280 ; U7.10@5726.5,7280 5770,7280 5780,7290 HDMI.1@5835,7290
  Top Layer w8: U7.1@5695,7280 U7.10@5726.5,7280
HDMI_TXC_N: HDMI.12 U6.37 U8.5 U8.6 | length 742.6
  Top Layer w6.5: U6.37@5442.63,6698.38 5463,6698.38 5466.35,6701.73 5575.73,6701.73 5654,6780 5654,7075 5667,7088 5690.52,7088 U8.5@5692.26,7086.26 ; 5678.06,7088 cw(c5678.06,7076.6) U8.5@5686.12,7084.66 ; U8.5@5693,7087 U8.5@5692.26,7086.26 ; U8.5@5695,7086.26 U8.5@5692.26,7086.26
  Top Layer w8: U8.5@5695,7086.26 U8.6@5726.5,7086.26 5762.2,7086.26 5775,7073.46 HDMI.12@5835,7073.46
HDMI_TXC_P: HDMI.10 U6.38 U8.4 U8.7 | length 745.5
  Top Layer w6.5: U6.38@5442.63,6718.07 5463,6718.07 5466.35,6714.73 5570.34,6714.73 5641,6785.38 5641,7081.25 5662.38,7102.62 5682.62,7102.62 U8.4@5685.95,7105.95 ; 5674.24,7102.62 ccw(c5674.24,7119.42) U8.4@5686.12,7107.55 ; 5676,7102.6 5679,7102.6 ; 5681.74,7101.74 cw(c5686.6,7096.88) U8.4@5687.44,7103.7 ; U8.4@5686,7105.95 U8.4@5685.95,7105.95 ; U8.4@5686,7106 U8.4@5685.95,7105.95
  Top Layer w8: U8.4@5695,7105.95 U8.7@5726.5,7105.95 5768.11,7105.95 5775,7112.83 HDMI.10@5835,7112.83
I2C0_SCL: J1.35 J4.18 U6.52 | length 3202.1
  Top Layer w6.5: J1.35@3926.44,5901.97 cw(c3911.19,5885) v1@3934,5885 ; J1.35@3930.63,5994.42 ccw(c3929.2,5999) 3934,5999 ; J1.35@3932.33,5983.4 cw(c3957.53,5986.6) 3939.57,6004.57 ; J1.35@3934,5938 v1@3934,5885 ; J1.35@3934,5947 3934,5999 ; J1.35@3937.37,5994.42 cw(c3938.8,5999) 3934,5999 ; J1.35@3938.78,5984.22 cw(c3974.17,5988.72) 3948.94,6013.94 ; J1.35@3941.56,5901.97 ccw(c3956.81,5885) v1@3934,5885 ; J1.35@3945.23,5985.04 cw(c3990.8,5990.83) 3958.32,6023.32 ; v1(3960,6185) 3958.32,6183.32 3958.32,6023.32 ; v1@4067,6300 4072,6300 4659,6887 v1@4659,7091 ; v1(5301,7091) 5299.25,7089.25 5299.25,7023.75 5359.93,6963.07 U6.52@5359.93,6938.62 ; 3934,5999 3958.32,6023.32
  Bottom Layer w6.5: v1@3936,5885 3936,5798.46 4222.46,5512 4289,5512 4309.79,5491.21 ; v1@3959,6191 v1@4067.5,6299.5 ; J4.18@4296.71,5464.55 ccw(c4276.07,5491.21) 4309.79,5491.21 ; J4.18@4300.69,5459.41 ccw(c4286.33,5477.96) 4309.79,5477.96 ccw(c4333.25,5477.96) J4.18@4318.88,5459.41 ; J4.18@4309.79,5442.74 4309.79,5491.21 ; J4.18@4322.86,5464.55 cw(c4343.51,5491.21) 4309.79,5491.21 ; v1@4659.88,7091 v1(5301,7091)
  other v1: 3935,5887 4073,6305 4659,7092
I2C0_SDA: J1.36 J4.17 U6.51 | length 3378.5
  Top Layer w6.5: J1.36@3926,6145.16 ccw(c3911.51,6159.65) v2@3932,6159.65 ; J1.36@3934,6100.54 3932,6102.54 v2(3932,6164) ccw(c3954.39,6164) J1.36@3940.85,6146.17 ; v1(4044,6321) 4616,6893 v1(4616,7045) ; v1(5331,7044) 5331,7013.66 5379.63,6965.03 U6.51@5379.63,6938.62
  Bottom Layer w6.5: v2(3932,6164) 3887.38,6164 3887.19,6164.19 ; v1(4044,6321) 3887.19,6164.19 ; 4272.79,5401 ccw(c4300.43,5428.64) J4.17@4306.48,5390.02 ; 4276.81,5396.98 cw(c4248.75,5368.92) J4.17@4288.43,5368.92 ; 4281.83,5391.96 ccw(c4302.88,5413.01) J4.17@4307.49,5383.6 ; 4287.91,5385.88 cw(c4270.95,5368.92) J4.17@4294.93,5368.92 ; J4.17@4309.79,5364 4270.33,5403.46 4270.33,5477.67 4259,5489 4206,5489 4169,5526 4057,5526 3860.96,5722.04 3860.96,6137.96 3887.19,6164.19 ; v1@4615,7044 v1(5331,7044)
I2C1_SCL: J1.37 J4.20 | length 794.2
  Top Layer w6.5: J1.37@3976.96,5901.52 cw(c3962.91,5883.83) v1@3985.5,5883.83 ; v1@3985.5,5883.88 3985.5,5945.5 J1.37@3984,5947 J1.37@3988.75,5951.75 ; v1@3985.5,5886.69 cw(c4007.7,5886.69) J1.37@3992,5902.38
  Bottom Layer w6.5: v1@3984,5883.88 3984,5787.23 4222.23,5549 4316,5549 4388.53,5476.47 ; J4.20@4382.32,5468.09 ccw(c4379.77,5476.47) 4388.53,5476.47 ; J4.20@4388.53,5442.74 4388.53,5476.47 ; J4.20@4394.74,5468.09 cw(c4397.28,5476.47) 4388.53,5476.47
  other v1: 3985,5887
I2C1_SDA: J1.38 J4.19 | length 1119.3
  Top Layer w6.5: J1.38@3976,6055.93 cw(c3956.68,6036.61) 3984,6036.61 cw(c4011.32,6036.61) J1.38@3992,6055.93 ; v1(3981,6033) 3984,6036 J1.38@3984,6100.54
  Bottom Layer w6.5: 3972,6024 3959,6011 3959,5793.85 4220.54,5532.31 4309.69,5532.31 4350,5492 4350,5402.53 J4.19@4388.53,5364 ; 4352.46,5400.07 ccw(c4378.29,5425.9) J4.19@4384.75,5389.94 ; 4355.55,5396.98 cw(c4327.49,5368.92) J4.19@4367.17,5368.92 ; 4361.26,5391.27 ccw(c4380.97,5410.99) J4.19@4385.9,5383.54 ; 4366.65,5385.88 cw(c4349.69,5368.92) J4.19@4373.67,5368.92
I2C2_SCL: J1.39 J4.22 | length 985.8
  Top Layer w6.5: J1.39@4026,5902.38 cw(c4011.51,5887.89) v1@4032,5887.89 ; v1@4032,5878 v1(4032,5887) 4032,5945 J1.39@4034,5947 J1.39@4034,5902 ; v1@4032,5886.92 cw(c4048.02,5886.92) J1.39@4039.8,5900.67
  Bottom Layer w6.5: v1@4032,5882 4032,5782 4234,5580 4330.01,5580 J4.22@4467.27,5442.74 ; 4422.41,5487.6 ccw(c4467.27,5532.46) J4.22@4467.27,5469.02 ; 4433.51,5476.5 ccw(c4467.27,5510.26) J4.22@4467.27,5462.52 ; 4434.29,5475.72 cw(c4406.23,5447.66) J4.22@4445.91,5447.66 ; 4444.6,5465.41 ccw(c4467.27,5488.07) J4.22@4467.27,5456.02 ; 4445.39,5464.62 cw(c4428.43,5447.66) J4.22@4452.41,5447.66
I2C2_SDA: J1.40 J4.21 | length 1139.7
  Top Layer w6.5: J1.40@4026,6055.93 cw(c4006.68,6036.61) 4034,6036.61 cw(c4061.32,6036.61) J1.40@4042,6055.93 ; v1(4034,6026.24) J1.40@4034,6100.54
  Bottom Layer w6.5: v1(4034,6026.24) 4009,6001.24 4009,5780.62 4224.82,5564.8 4325.2,5564.8 4428,5462 4428,5417 4467.27,5377.73 J4.21@4467.27,5364 ; 4435.68,5409.32 cw(c4395.27,5368.92) J4.21@4452.41,5368.92 ; 4445.85,5399.15 ccw(c4467.27,5420.56) J4.21@4467.27,5390.28 ; 4446.77,5398.23 cw(c4417.47,5368.92) J4.21@4458.91,5368.92
JTAG_EMU0: J1.63 JTAG.13 R72.2 | length 1127.8
  Top Layer w6.5: 4302.2,5633.8 ccw(c4316.38,5647.97) JTAG.13@4325.66,5630.2 ; 4305.22,5630.78 cw(c4284.84,5610.4) JTAG.13@4313.66,5610.4 ; 4308.46,5627.54 ccw(c4320.67,5639.75) JTAG.13@4328.67,5624.44 ; JTAG.13@4336,5573 4336,5600 4297,5639 4297,5794 4304,5801 4557,5801 v1(4634,5878) J1.63@4634,5947 ; J1.63@4626,5902.38 cw(c4606.68,5883.06) 4634,5883.06 cw(c4661.32,5883.06) J1.63@4642,5902.38
  Bottom Layer w6.5: R72.2@4609.57,6105.57 cw(c4572.32,6068.32) 4625,6068.32 ; R72.2@4614.17,6110.17 cw(c4588.01,6084.01) 4625,6084.01 ; R72.2@4620,6119 4625,6114 4625,5878 v1(4634,5878) ; 4625,6092.46 cw(c4643.54,6092.46) R72.2@4630.43,6105.57
JTAG_EMU1: J1.65 JTAG.14 R73.2 | length 1220.1
  Top Layer w6.5: JTAG.14@4312.5,5735.92 ccw(c4329.15,5755.4) JTAG.14@4347.28,5737.28 ; JTAG.14@4316.72,5740.86 ccw(c4333.74,5760.75) JTAG.14@4352.24,5742.24 ; JTAG.14@4320.95,5745.8 ccw(c4338.32,5766.11) JTAG.14@4357.21,5747.21 ; JTAG.14@4325.17,5750.74 ccw(c4342.9,5771.47) 4362.18,5752.18 ; JTAG.14@4329.4,5755.68 ccw(c4347.48,5776.83) 4367.15,5757.15 ; JTAG.14@4333.62,5760.62 ccw(c4352.06,5782.18) 4372.12,5762.12 ; JTAG.14@4336,5726 4392,5782 ; JTAG.14@4337.85,5765.56 ccw(c4356.64,5787.54) 4377.09,5767.09 ; JTAG.14@4342.07,5770.5 ccw(c4361.22,5792.9) 4382.06,5772.06 ; JTAG.14@4346.29,5775.44 ccw(c4365.8,5798.26) 4387.03,5777.03 ; JTAG.14@4350.52,5780.38 ccw(c4370.38,5803.61) 4392,5782 ; J1.65@4676,5991.62 ccw(c4656.68,6010.94) 4684,6010.94 ccw(c4711.32,6010.94) J1.65@4692,5991.62 ; J1.65@4676.69,5901.74 cw(c4663.39,5886) 4684,5886 ; v1(4684,6019) J1.65@4684,5947 4684,5886 ; J1.65@4691.31,5901.74 ccw(c4704.61,5886) 4684,5886 ; 4392,5782 4580,5782 4684,5886
  Bottom Layer w6.5: R73.2@4674.57,6105.57 cw(c4651.8,6082.8) 4684,6082.8 ; v1(4684,6019) 4684,6118 R73.2@4685,6119 ; 4684,6077.98 cw(c4723.02,6077.98) R73.2@4695.43,6105.57 ; 4684,6093.67 cw(c4707.33,6093.67) R73.2@4690.83,6110.17
JTAG_TCK: J1.61 JTAG.9 JTAG.11 | length 1582.8
  Top Layer w6.5: JTAG.9@4173.35,5513.75 cw(c4172.12,5508) 4178,5508 ; JTAG.9@4178,5573 4178,5508 ; JTAG.9@4178,5575 4254.7,5575 JTAG.11@4256.7,5573 ; JTAG.9@4182.65,5513.75 ccw(c4183.88,5508) 4178,5508 ; JTAG.9@4184.6,5566.4 cw(c4205.38,5545.62) 4205.38,5575 ; JTAG.9@4189.2,5561.8 cw(c4221.07,5529.93) 4221.07,5575 ; JTAG.9@4189.2,5584.2 ccw(c4211.41,5606.41) 4211.41,5575 ; JTAG.9@4193.8,5557.2 cw(c4236.76,5514.24) JTAG.11@4236.76,5575 ; JTAG.9@4193.8,5588.8 ccw(c4227.11,5622.11) 4227.11,5575 ; JTAG.9@4197.94,5575 cw(c4197.94,5514.24) JTAG.11@4240.9,5557.2 ; 4207.6,5575 ccw(c4207.6,5622.11) JTAG.11@4240.9,5588.8 ; 4213.63,5575 cw(c4213.63,5529.93) JTAG.11@4245.5,5561.8 ; 4223.29,5575 ccw(c4223.29,5606.41) JTAG.11@4245.5,5584.2 ; 4229.32,5575 cw(c4229.32,5545.62) JTAG.11@4250.1,5566.4 ; J1.61@4576,5902.38 cw(c4556.68,5883.06) 4584,5883.06 cw(c4611.32,5883.06) J1.61@4592,5902.38 ; J1.61@4584,5947 4584,5876 4535,5827 4122,5827 4094,5799 4067,5799 4057,5789 4057,5512 4073,5496 4166,5496 4178,5508
JTAG_TDI: J1.62 JTAG.3 | length 1144.9
  Top Layer w6.5: JTAG.3@3941.74,5573 3960.14,5573 3979,5591.86 3979,5801 3990,5812 4088,5812 4117,5841 4527,5841 4558.32,5872.32 4558.32,6003.32 4584,6029 J1.62@4584,6100.54 ; J1.62@4576,6055.93 cw(c4556.68,6036.61) 4584,6036.61 cw(c4611.32,6036.61) J1.62@4592,6055.93
JTAG_TDO: J1.64 JTAG.7 | length 1021.8
  Top Layer w6.5: JTAG.7@4099.22,5573 4137,5610.78 4137,5800 4151,5814 4545,5814 4609.68,5878.68 4609.68,6012.68 4634,6037 ; J1.64@4626.08,6055.85 cw(c4607.62,6037) 4634,6037 ; J1.64@4634,6100.54 4634,6037 ; J1.64@4641.92,6055.85 ccw(c4660.38,6037) 4634,6037
JTAG_TMS: J1.59 JTAG.1 | length 1038.1
  Top Layer w6.5: JTAG.1@3863,5573 3876,5573 3898.34,5595.34 3898.34,5808.34 3915,5825 4080,5825 4109,5854 4517,5854 4534,5871 J1.59@4534,5947 ; J1.59@4526,5902.38 cw(c4506.68,5883.06) 4534,5883.06 cw(c4561.32,5883.06) J1.59@4542,5902.38
JTAG_TRSTN: J1.60 JTAG.2 R74.2 | length 1416.5
  Top Layer w6.5: JTAG.2@3849.01,5780.82 ccw(c3825.58,5810) 3863,5810 ; JTAG.2@3853.08,5775.75 ccw(c3836.47,5796.44) 3863,5796.44 ccw(c3889.53,5796.44) JTAG.2@3872.92,5775.75 ; JTAG.2@3863,5726 3863,5810 ; JTAG.2@3876.99,5780.82 cw(c3900.42,5810) 3863,5810 ; 4520.47,6039.47 ccw(c4508.33,6051.6) J1.60@4523.8,6059.03 ; 4526.95,6045.95 ccw(c4517.09,6055.81) J1.60@4529.66,6061.84 ; J1.60@4534,6100.54 4534,6053 4515,6034 v1(4507,6034) 4508.32,6032.68 4508.32,5873.32 4503,5868 4103,5868 4073,5838 3891,5838 3863,5810
  Bottom Layer w6.5: 4464.47,6151.97 ccw(c4438.43,6178) R74.2@4475.25,6178 ; 4465.67,6153.17 cw(c4490,6128.85) R74.2@4490,6163.25 ; 4475.56,6163.06 ccw(c4460.63,6178) R74.2@4481.75,6178 ; 4476.77,6164.27 cw(c4490,6151.04) R74.2@4490,6169.75 ; R74.2@4490,6181 4490,6177.5 4462.25,6149.75 4462.25,6077.75 v1@4506.5,6033.5
LCD_DATA0: C58.1 J2.76 J5.29 R16.2 R40.1 U6.15 | length 2496
  Top Layer w6.5: C58.1@4606.7,7657.57 ccw(c4625.43,7652.88) 4611.77,7639.23 ; C58.1@4613,7655.99 ccw(c4638.4,7649.63) 4619.89,7631.11 ; C58.1@4619.31,7654.41 ccw(c4651.38,7646.38) v1@4628,7623 ; v1@4627.5,7610.5 4639.5,7610.5 4661,7589 4743.62,7589 4786.62,7546 4852,7546 4934,7464 J2.76@4934,7397.54 4934,7333 4909.68,7308.68 4909.68,7145.08 4909.75,7145.01 4909.75,7126.99 4909.68,7126.92 4909.68,6758.32 5028.7,6639.3 U6.15@5100,6639.3 ; v1(4634,7617) 4605,7646 C58.1@4605,7661 4592,7661 4571,7682 4571,7739 4648,7816 4709,7816 4782.36,7889.36 J5.29@4782.36,7900 ; 4741.86,7848.86 ccw(c4695.65,7895.08) J5.29@4761.01,7895.08 ; 4752.96,7859.96 ccw(c4717.84,7895.08) J5.29@4767.51,7895.08 ; 4755.66,7862.66 cw(c4782.36,7835.97) J5.29@4782.36,7873.72 ; 4764.05,7871.05 ccw(c4740.03,7895.08) J5.29@4774.01,7895.08 ; 4766.76,7873.76 cw(c4782.36,7858.16) J5.29@4782.36,7880.22 ; J2.76@4926,7352.93 cw(c4906.68,7333.61) 4934,7333.61 cw(c4961.32,7333.61) J2.76@4942,7352.93 ; J2.76@4926,7442.16 ccw(c4906.68,7461.48) 4934,7461.48 ccw(c4961.32,7461.48) J2.76@4942,7442.16
  Bottom Layer w6.5: R40.1@4593.57,7579.43 ccw(c4568.39,7604.61) 4604,7604.61 ccw(c4639.61,7604.61) R40.1@4614.43,7579.43 ; R16.2@4594.57,7647.57 cw(c4571.8,7624.8) 4604,7624.8 ; R40.1@4598.17,7574.83 ccw(c4584.08,7588.92) 4604,7588.92 ccw(c4623.92,7588.92) R40.1@4609.83,7574.83 ; R40.1@4604,7566 R16.2@4604,7647 ; 4604,7619.98 cw(c4643.02,7619.98) R16.2@4615.43,7647.57 ; 4604,7635.67 cw(c4627.33,7635.67) R16.2@4610.83,7652.17 ; R16.2@4604,7660 R16.2@4604,7647 ; R16.2@4606.7,7657.57 ccw(c4625.43,7652.88) 4611.77,7639.23 ; R16.2@4613,7655.99 ccw(c4638.4,7649.63) 4619.89,7631.11 ; R16.2@4619.31,7654.41 ccw(c4651.38,7646.38) v1@4628,7623 ; v1(4634,7617) R16.2@4604,7647 ; J5.29@4782.36,7876.36 J5.29@4782.36,7900
LCD_DATA1: C59.1 J2.75 J5.30 R15.2 R39.1 U6.13 | length 2329.3
  Top Layer w6.5: 4642.5,7688.5 ccw(c4666.37,7712.36) C59.1@4668.89,7678.71 ; 4646.94,7684.06 cw(c4626.88,7664) C59.1@4655.25,7664 ; 4652.52,7678.48 ccw(c4667.77,7693.73) C59.1@4669.38,7672.23 ; C59.1@4659.92,7647.23 cw(c4638.19,7624) v1(4670,7624) ; C59.1@4664.36,7651.98 cw(c4652.21,7638.98) 4670,7638.98 cw(c4687.79,7638.98) C59.1@4675.64,7651.98 ; C59.1@4680.08,7647.23 ccw(c4701.81,7624) v1(4670,7624) ; J5.30@4782.36,7978.74 4821,7940.1 4821,7885 4816.75,7880.75 4816.62,7880.75 4803.25,7867.38 4803.25,7867.25 4733,7797 4694,7797 4641,7744 4641,7690 C59.1@4670,7661 v1(4670,7624) ; J5.30@4782.93,7965.48 cw(c4784.71,7939.34) 4803.24,7957.87 ; J5.30@4783.37,7959 cw(c4785.99,7920.4) 4813.35,7947.76 ; J5.30@4797.22,7973.82 ccw(c4821.2,7973.82) 4804.24,7956.86 ; J5.30@4803.72,7973.82 ccw(c4843.4,7973.82) 4815.34,7945.76 ; J2.75@4926,7199.38 cw(c4906.68,7180.06) 4934,7180.06 cw(c4961.32,7180.06) J2.75@4942,7199.38 ; J2.75@4926.65,7289.22 ccw(c4913.06,7305.15) 4934,7305.15 ; J2.75@4941.35,7289.22 cw(c4954.94,7305.15) 4934,7305.15 ; U6.13@5100,6678.69 5053.31,6678.69 4934,6798 J2.75@4934,7244 4934,7305.15 ; v1(4670,7624) 4692,7602 4749,7602 4790.65,7560.35 4863.65,7560.35 4958.32,7465.68 4958.32,7329.47 4934,7305.15
  Bottom Layer w6.5: R39.1@4658.57,7579.43 ccw(c4633.39,7604.61) 4669,7604.61 ccw(c4704.61,7604.61) R39.1@4679.43,7579.43 ; R15.2@4659.92,7647.23 cw(c4638.19,7624) v1(4670,7624) ; R39.1@4663.17,7574.83 ccw(c4649.08,7588.92) 4669,7588.92 ccw(c4688.92,7588.92) R39.1@4674.83,7574.83 ; R15.2@4664.36,7651.98 cw(c4652.21,7638.98) 4670,7638.98 cw(c4687.79,7638.98) R15.2@4675.64,7651.98 ; R39.1@4669,7566 4669,7612 ; R15.2@4670,7676 R15.2@4670,7661 v1(4670,7624) ; R15.2@4680.08,7647.23 ccw(c4701.81,7624) v1(4670,7624)
LCD_DATA2: BOOT.1 C60.1 J2.78 J5.31 R14.2 U6.12 | length 3622.3
  Top Layer w6.5: BOOT.1@3277.05,7890.19 ccw(c3259.08,7908.17) 3284.5,7908.17 ccw(c3309.92,7908.17) BOOT.1@3291.95,7890.19 ; BOOT.1@3284.5,7867 v1@3284.5,7912.5 ; 4709.75,7684.25 ccw(c4725.8,7700.3) C60.1@4731.38,7678.3 ; 4713.36,7680.64 cw(c4696.71,7664) C60.1@4720.25,7664 ; 4717.84,7676.16 ccw(c4729.07,7687.39) C60.1@4732.97,7672 ; C60.1@4733,7661 4707.25,7686.75 4707.25,7746.01 4820.24,7859 4825,7859 v1(4826,7858) ; C60.1@4735,7643.25 cw(c4735,7631.78) 4743.11,7639.89 ; C60.1@4735,7648 v1(4763,7620) 4809.65,7573.35 4877.65,7573.35 4984,7467 J2.78@4984,7397.54 4984,7326.38 4958.32,7300.7 4958.32,6799.68 5059.62,6698.38 U6.12@5100,6698.38 ; C60.1@4743.05,7656.18 ccw(c4767.08,7650.76) 4749.66,7633.34 ; C60.1@4749.39,7654.75 ccw(c4780.69,7647.69) v1@4758,7625 ; v1@4822.55,7861.45 J5.31@4861.1,7900 4861.1,7892.1 J5.31@4860.1,7892.1 ; v1@4828.13,7867.02 ccw(c4800.07,7895.08) J5.31@4839.75,7895.08 ; v1@4830.18,7869.08 cw(c4857.4,7841.86) J5.31@4860.07,7880.26 ; 4839.22,7878.12 ccw(c4822.26,7895.08) J5.31@4846.25,7895.08 ; 4840.27,7879.17 cw(c4858.71,7860.73) J5.31@4860.52,7886.74 ; J2.78@4976,7352.93 cw(c4956.68,7333.61) 4984,7333.61 cw(c5011.32,7333.61) J2.78@4992,7352.93 ; J2.78@4976,7442.16 ccw(c4956.68,7461.48) 4984,7461.48 ccw(c5011.32,7461.48) J2.78@4992,7442.16
  Bottom Layer w6.5: v1(3285,7915) 3414,7915 3503,7826 4792,7826 4825,7859 v1(4826,7858) ; R14.2@4735,7643.25 cw(c4735,7631.78) 4743.11,7639.89 ; R14.2@4735,7661 4735,7648 v1(4763,7620) ; R14.2@4743.05,7656.18 ccw(c4767.08,7650.76) 4749.66,7633.34 ; R14.2@4749.39,7654.75 ccw(c4780.69,7647.69) v1@4758,7625
LCD_DATA3: C61.1 J2.77 J5.32 R13.2 R37.1 U6.11 | length 2133.4
  Top Layer w6.5: 4773.75,7687.25 ccw(c4794.96,7708.46) C61.1@4798.34,7678.66 ; 4776.94,7684.06 cw(c4756.88,7664) C61.1@4785.25,7664 ; 4783.29,7677.71 ccw(c4796.9,7691.33) C61.1@4799.07,7672.2 ; C61.1@4789.7,7647.44 cw(c4765.85,7623) v1(4800,7623) ; C61.1@4794.24,7652.09 cw(c4780.9,7638.42) 4800,7638.42 cw(c4819.1,7638.42) C61.1@4805.76,7652.09 ; v1@4799.5,7622.5 4834,7588 4887,7588 5008.32,7466.68 5008.32,7332.32 4984,7308 J2.77@4984,7244 4982,7242 4982,6798 5061.93,6718.07 U6.11@5100,6718.07 ; C61.1@4810.3,7647.44 ccw(c4834.15,7623) v1(4800,7623) ; J5.32@4861.1,7978.74 4871.26,7978.74 4900,7950 4900,7886 4772.25,7758.25 4772.25,7688.75 C61.1@4800,7661 v1(4800,7623) ; J5.32@4863.32,7965.76 cw(c4871.09,7937.6) 4891.74,7958.26 ; J5.32@4865.05,7959.5 cw(c4874.5,7925.22) 4899.64,7950.36 ; J5.32@4882.46,7973.82 ccw(c4897.62,7973.82) 4886.9,7963.1 ; J2.77@4976,7199.38 cw(c4961.51,7184.89) 4982,7184.89 ; J2.77@4976,7288.62 ccw(c4956.68,7307.94) 4984,7307.94 ccw(c5011.32,7307.94) J2.77@4992,7288.62 ; 4982,7175.24 cw(c5016.15,7175.24) J2.77@4992,7199.38 ; 4982,7190.93 cw(c5000.46,7190.93) J2.77@4987.41,7203.98
  Bottom Layer w6.5: R37.1@4788.57,7579.43 ccw(c4763.39,7604.61) 4799,7604.61 ccw(c4834.61,7604.61) R37.1@4809.43,7579.43 ; R13.2@4789.7,7647.44 cw(c4765.85,7623) v1(4800,7623) ; R37.1@4793.17,7574.83 ccw(c4779.08,7588.92) 4799,7588.92 ccw(c4818.92,7588.92) R37.1@4804.83,7574.83 ; R13.2@4794.24,7652.09 cw(c4780.9,7638.42) 4800,7638.42 cw(c4819.1,7638.42) R13.2@4805.76,7652.09 ; R37.1@4799,7566 4799,7611 ; R13.2@4800,7661 v1(4800,7623) ; R13.2@4810.3,7647.44 ccw(c4834.15,7623) v1(4800,7623)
